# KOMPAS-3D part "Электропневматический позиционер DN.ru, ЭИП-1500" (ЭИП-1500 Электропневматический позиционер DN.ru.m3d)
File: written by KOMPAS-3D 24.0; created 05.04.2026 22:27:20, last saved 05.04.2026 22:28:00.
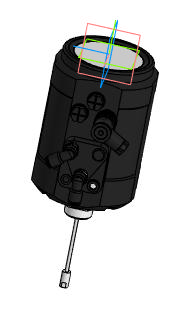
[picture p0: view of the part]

Document properties: Автор: R2D2; Полное имя файла: E:\Работа\Зайцев\Аксессуары для пневмоприводов\Электропневматические позиционеры DN.ru\ЭИП Электропневматический позиционер DN.ru\ЭИП-1500 Электропневматический позиционер DN.ru\25-50\ЭИП-1500 Электропневматический позиционер DN.ru.m3d

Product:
- Part/product: Электропневматический позиционер DN.ru  | designation ЭИП-1500
    Масса: 0.14
    Раздел спецификации: Прочие изделия
    Примечание: D900-02859

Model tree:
1. Операция без истории:1

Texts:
  ЭИП-1500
